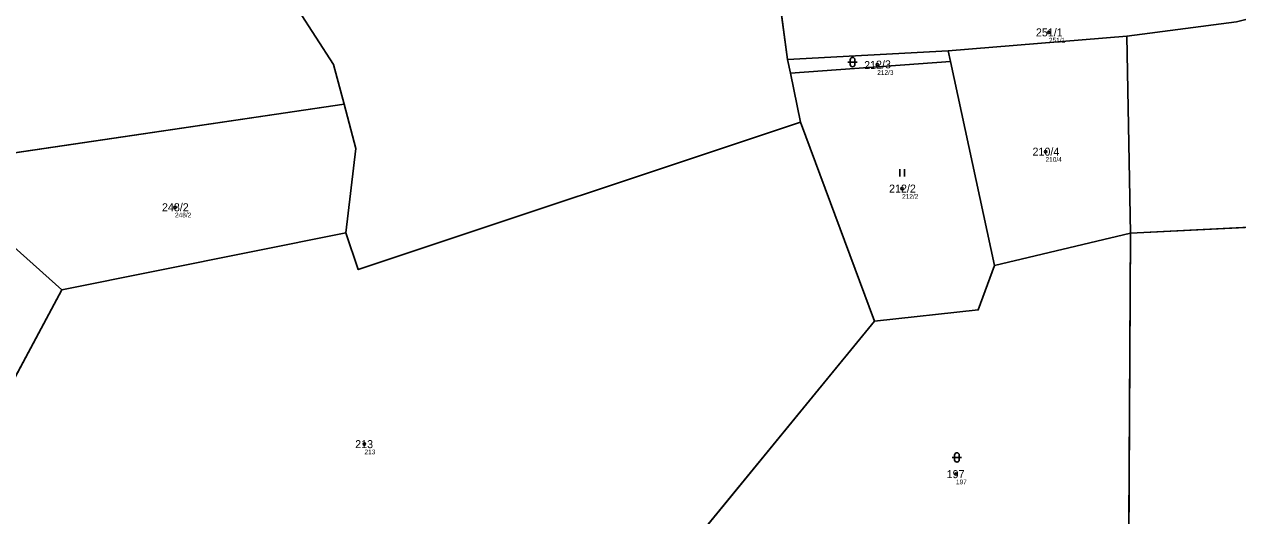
# Model space of a CAD drawing. Extents: x -766177 to -763254, y -1057727 to -1053915.
# Drawn here: x -764321.8 to -764063.9, y -1057510.3 to -1057405.8 of the extents above; entities that cross this region are included whole.
import ezdxf

# ---------------------------------------------------------------- set-up
doc = ezdxf.new("R2010")
doc.units = 0
for name, color, linetype in [('Vrstva 1', 7, 'Continuous'), ('Vrstva 2', 7, 'Continuous'), ('Vrstva 3', 7, 'Continuous'), ('Vrstva 50', 7, 'Continuous'), ('Vrstva 51', 7, 'Continuous')]:
    doc.layers.add(name, color=color, linetype=linetype)

msp = doc.modelspace()

# ---------------------------------------------------------------- linework, layer by layer
at = {"layer": 'Vrstva 1'}
for p, q in [((-764159.59, -1057413.32), (-764165.78, -1057367.54)), ((-764087.47, -1057408.35), (-764125.46, -1057411.43)), ((-764086.71, -1057450.26), (-764087.47, -1057408.35)), ((-764125.46, -1057411.43), (-764159.59, -1057413.32)), ((-764125.46, -1057411.43), (-764124.96, -1057413.73)), ((-764159.59, -1057413.32), (-764159, -1057416.2)), ((-764124.96, -1057413.73), (-764159, -1057416.2)), ((-764124.96, -1057413.73), (-764115.62, -1057457.1)), ((-764159, -1057416.2), (-764156.86, -1057426.65)), ((-764334.97, -1057434.81), (-764253.82, -1057422.79)), ((-764156.86, -1057426.65), (-764141.1, -1057468.91)), ((-764038.99, -1057447.79), (-764086.71, -1057450.26)), ((-764253.46, -1057450.18), (-764313.8, -1057462.31)), ((-764086.71, -1057450.26), (-764115.62, -1057457.1)), ((-764087.13, -1057524.45), (-764086.71, -1057450.26)), ((-764313.8, -1057462.31), (-764355.39, -1057539.97)), ((-764141.1, -1057468.91), (-764185.45, -1057523.11))]:
    msp.add_line(p, q, dxfattribs=at)
for points in [[(-764253.82, -1057422.79), (-764256.07, -1057414.34), (-764263.57, -1057402.71), (-764319.34, -1057371.35)], [(-764014.26, -1057390.97), (-764037.37, -1057398.48), (-764064.23, -1057405.28), (-764087.47, -1057408.35)], [(-764253.46, -1057450.18), (-764251.32, -1057432.22), (-764253.82, -1057422.79)], [(-764156.86, -1057426.65), (-764250.82, -1057457.98), (-764253.46, -1057450.18)], [(-764313.8, -1057462.31), (-764332.76, -1057445.36), (-764334.97, -1057434.81)], [(-764115.62, -1057457.1), (-764119.09, -1057466.57), (-764141.1, -1057468.91)]]:
    msp.add_lwpolyline(points, dxfattribs=at)
at = {"layer": 'Vrstva 3'}
for p, q in [((-764146.781, -1057413.851), (-764144.779, -1057413.851)), ((-764146.281, -1057413.351), (-764146.281, -1057414.352)), ((-764145.279, -1057414.352), (-764145.279, -1057413.351)), ((-764135.761, -1057438.15), (-764135.761, -1057436.65)), ((-764134.76, -1057438.15), (-764134.76, -1057436.65)), ((-764124.101, -1057497.431), (-764124.101, -1057498.432)), ((-764123.099, -1057498.432), (-764123.099, -1057497.431)), ((-764124.601, -1057497.931), (-764122.599, -1057497.931))]:
    msp.add_line(p, q, dxfattribs=at)
for centre, start, end in [((-764145.78, -1057413.3509), 0, 180), ((-764145.78, -1057414.3509), 180, 359.9878861), ((-764123.6, -1057497.4309), 0, 180), ((-764123.6, -1057498.4309), 180, 359.9878861)]:
    msp.add_arc(centre, 0.5, start, end, dxfattribs=at)
at = {"layer": 'Vrstva 50'}
for centre in [(-764104.05, -1057407.52994), (-764140.54, -1057414.40994), (-764104.77, -1057432.89994), (-764135.25, -1057440.74994), (-764289.75, -1057444.71994), (-764249.49, -1057495.09994), (-764123.81, -1057501.47994)]:
    msp.add_circle(centre, 0.25, dxfattribs=at)
at = {"layer": 'Vrstva 51'}
for points in [[(-764285.91, -1057335.97), (-764319.34, -1057371.35), (-764263.57, -1057402.71), (-764256.07, -1057414.34), (-764253.82, -1057422.79), (-764251.32, -1057432.22), (-764253.46, -1057450.18), (-764250.82, -1057457.98), (-764156.86, -1057426.65), (-764159, -1057416.2), (-764159.59, -1057413.32), (-764165.78, -1057367.54), (-764171.13, -1057339.9), (-764181.87, -1057298.13), (-764190.59, -1057290.5), (-764208.89, -1057293.05), (-764223.11, -1057295.67), (-764254.56, -1057306.64)], [(-764319.34, -1057371.35), (-764342.38, -1057356.59), (-764351.27, -1057349.78), (-764359.13, -1057353.06), (-764357.78, -1057383.9), (-764348.79, -1057403.57), (-764337.64, -1057422.08), (-764334.97, -1057434.81), (-764253.82, -1057422.79), (-764256.07, -1057414.34), (-764263.57, -1057402.71)], [(-763990.95, -1057364.41), (-764067.95, -1057397.29), (-764089.05, -1057402.01), (-764126.17, -1057399.6), (-764165.78, -1057367.54), (-764159.59, -1057413.32), (-764125.46, -1057411.43), (-764087.47, -1057408.35), (-764064.23, -1057405.28), (-764037.37, -1057398.48), (-764014.26, -1057390.97), (-763987.65, -1057375)], [(-764064.23, -1057405.28), (-764087.47, -1057408.35), (-764086.71, -1057450.26), (-764038.99, -1057447.79), (-764011.66, -1057436.02), (-764008.88, -1057415.7), (-764011.51, -1057403.59), (-764014.26, -1057390.97), (-764037.37, -1057398.48)], [(-764087.47, -1057408.35), (-764125.46, -1057411.43), (-764124.96, -1057413.73), (-764115.62, -1057457.1), (-764086.71, -1057450.26)], [(-764125.46, -1057411.43), (-764159.59, -1057413.32), (-764159, -1057416.2), (-764124.96, -1057413.73)], [(-764124.96, -1057413.73), (-764159, -1057416.2), (-764156.86, -1057426.65), (-764141.1, -1057468.91), (-764119.09, -1057466.57), (-764115.62, -1057457.1)], [(-764251.32, -1057432.22), (-764253.82, -1057422.79), (-764334.97, -1057434.81), (-764332.76, -1057445.36), (-764313.8, -1057462.31), (-764253.46, -1057450.18)], [(-764255.03, -1057534.6), (-764240.51, -1057532.15), (-764208.78, -1057524.32), (-764198.02, -1057522.93), (-764188.72, -1057522.77), (-764185.45, -1057523.11), (-764141.1, -1057468.91), (-764156.86, -1057426.65), (-764250.82, -1057457.98), (-764253.46, -1057450.18), (-764313.8, -1057462.31), (-764355.39, -1057539.97), (-764323.11, -1057539.17), (-764306.27, -1057537.86), (-764273.35, -1057536.41)], [(-764038.99, -1057447.79), (-764086.71, -1057450.26), (-764087.13, -1057524.45), (-764055.65, -1057518.01), (-764026.56, -1057513.08), (-764021.64, -1057485.2), (-764015.6, -1057455.43)], [(-764152.83, -1057529.46), (-764124.6, -1057532.75), (-764110.51, -1057531.64), (-764087.13, -1057524.45), (-764086.71, -1057450.26), (-764115.62, -1057457.1), (-764119.09, -1057466.57), (-764141.1, -1057468.91), (-764185.45, -1057523.11)]]:
    msp.add_lwpolyline(points, close=True, dxfattribs=at)
msp.add_lwpolyline([(-764355.39, -1057539.97), (-764313.8, -1057462.31), (-764332.76, -1057445.36)], dxfattribs=at)

# ---------------------------------------------------------------- texts
at = {"layer": 'Vrstva 2'}
for s, p in [('251/1', (-764106.823, -1057408.38)), ('210/4', (-764107.543, -1057433.75)), ('212/2', (-764138.023, -1057441.6)), ('248/2', (-764292.523, -1057445.57)), ('213', (-764251.464, -1057495.95)), ('197', (-764125.784, -1057502.33))]:
    msp.add_text(s, height=1.699998, dxfattribs=at).set_placement(p)
msp.add_text('212/3', height=1.699998, rotation=2, dxfattribs=at).set_placement((-764143.282, -1057415.356))
at = {"layer": 'Vrstva 50'}
for s, p in [('251/1', (-764104.05, -1057409.686)), ('212/3', (-764140.54, -1057416.566)), ('210/4', (-764104.77, -1057435.056)), ('212/2', (-764135.25, -1057442.906)), ('248/2', (-764289.75, -1057446.876)), ('213', (-764249.49, -1057497.256)), ('197', (-764123.81, -1057503.636))]:
    msp.add_text(s, height=0.999996, dxfattribs=at).set_placement(p)

doc.saveas('drawing.dxf')
